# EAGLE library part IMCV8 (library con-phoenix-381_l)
Invertierter Mini-Combicon 3.81mm vertikal 8-polig IMCV 1,5/8-G-3,81 (ohne Gegenstecker)
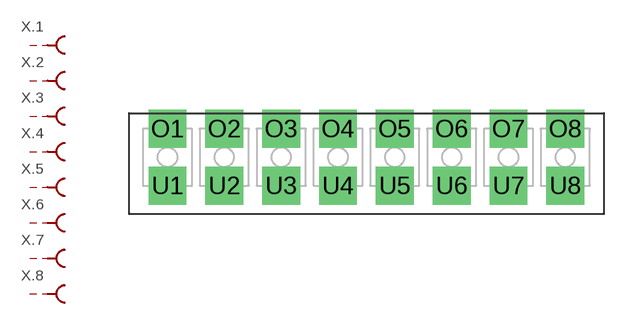
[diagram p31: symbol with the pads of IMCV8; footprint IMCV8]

Designator prefix X; gates .4=MCBU .3=MCBU .2=MCBU .1=MCBU .5=MCBU .6=MCBU .7=MCBU .8=MCBU

## IMCV8  [IMCV8]
O1  .1:S  pas
O2  .2:S  pas
O3  .3:S  pas
O4  .4:S  pas
O5  .5:S  pas
O6  .6:S  pas
O7  .7:S  pas
O8  .8:S  pas
U1  .1:SK  pas
U2  .2:SK  pas
U3  .3:SK  pas
U4  .4:SK  pas
U5  .5:SK  pas
U6  .6:SK  pas
U7  .7:SK  pas
U8  .8:SK  pas

## Footprint IMCV8 (pad centres in mm)
Mini-Combicon 3.81mm vertical 8-polig invertiert (ohne Gegenstecker)
drill 1.3 pad 2.54 square: O1 -13.335,1.905; O2 -9.525,1.905; O3 -5.715,1.905; O4 -1.905,1.905; O5 1.905,1.905; O6 5.715,1.905; O7 9.525,1.905; O8 13.335,1.905; U1 -13.335,-1.905; U2 -9.525,-1.905; U3 -5.715,-1.905; U4 -1.905,-1.905; U5 1.905,-1.905; U6 5.715,-1.905; U7 9.525,-1.905; U8 13.335,-1.905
